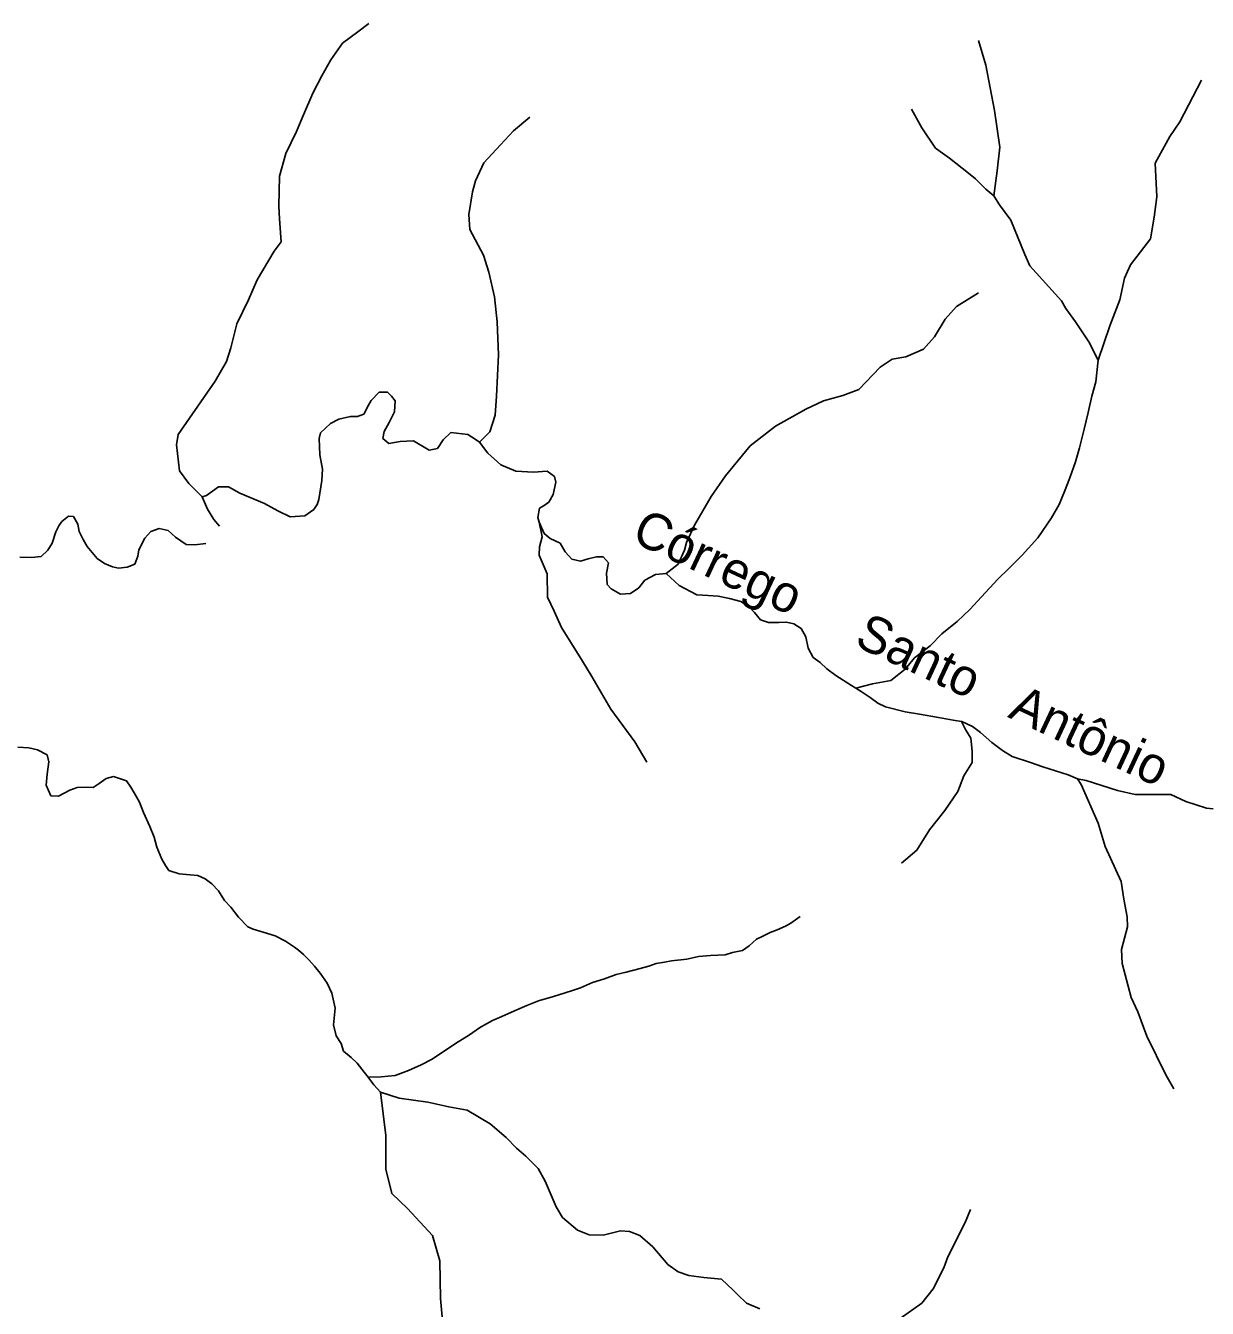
# Model space of a CAD drawing. Extents: x 717.8 to 772.7, y 8672.2 to 8728.
# Drawn here: x 755.19 to 761.61, y 8693.87 to 8700.84 of the extents above; entities that cross this region are included whole.
import ezdxf
from ezdxf.enums import TextEntityAlignment as Align

# ---------------------------------------------------------------- set-up
doc = ezdxf.new("R2010")
doc.units = 0
doc.header["$LTSCALE"] = 0.08
doc.linetypes.add('LONG_DASHED', pattern=[7.5, 6, -1.5])
doc.layers.add('61', color=7, linetype='Continuous')
doc.layers.add('9', color=7, linetype='LONG_DASHED', lineweight=25)

msp = doc.modelspace()

# ---------------------------------------------------------------- linework, layer by layer
at = {"layer": '9'}
for points in [[(757.05, 8700.8522), (756.9906, 8700.8076), (756.9081, 8700.7469), (756.8446, 8700.6562), (756.7959, 8700.5686), (756.7458, 8700.4736), (756.6961, 8700.3565), (756.6567, 8700.2658), (756.5987, 8700.1461), (756.5654, 8700.0229), (756.5623, 8699.86), (756.566, 8699.7909), (756.5738, 8699.6668), (756.5367, 8699.6149), (756.4442, 8699.4594), (756.3961, 8699.3508), (756.3332, 8699.2212), (756.2999, 8699.0904), (756.2778, 8699.0164), (756.2161, 8698.909), (756.0755, 8698.7078), (756.015, 8698.619), (756.0052, 8698.5635), (756.0226, 8698.4224), (756.0718, 8698.352), (756.1444, 8698.2809)], [(760.3633, 8700.7609), (760.4041, 8700.6264), (760.4504, 8700.3804), (760.4801, 8700.1802), (760.4658, 8700.053), (760.447, 8699.9155)], [(761.576, 8700.5442), (761.4576, 8700.3183), (761.4027, 8700.2393), (761.3237, 8700.0933), (761.333, 8699.9108), (761.3182, 8699.7995), (761.2987, 8699.6834), (761.1902, 8699.5413), (761.1567, 8699.4685), (761.1313, 8699.3518), (761.0781, 8699.2106), (761.0145, 8699.0224)], [(759.9994, 8700.3873), (760.0551, 8700.2855), (760.1298, 8700.1754), (760.2057, 8700.1212), (760.3095, 8700.0395), (760.3477, 8700.009), (760.403, 8699.9532), (760.447, 8699.9155)], [(757.9263, 8700.3432), (757.8373, 8700.269), (757.7667, 8700.1937), (757.6757, 8700.0949), (757.6302, 8699.9979), (757.614, 8699.9378), (757.5942, 8699.8141), (757.5994, 8699.7342), (757.6736, 8699.5941), (757.7032, 8699.5015), (757.7332, 8699.3667), (757.7487, 8699.231), (757.7547, 8699.0529), (757.7436, 8698.8266), (757.7367, 8698.7244), (757.7079, 8698.6338), (757.6519, 8698.5771)], [(760.447, 8699.9155), (760.4778, 8699.8677), (760.5395, 8699.784), (760.6156, 8699.598), (760.6418, 8699.5351), (760.8152, 8699.3451), (760.8389, 8699.304), (760.8904, 8699.2309), (760.9639, 8699.1226), (761.0145, 8699.0224)], [(760.363, 8699.3883), (760.2438, 8699.3147), (760.1831, 8699.2464), (760.1237, 8699.1501), (760.0643, 8699.0833), (759.9681, 8699.0408), (759.8937, 8699.0281), (759.8294, 8698.985), (759.7128, 8698.8632), (759.6265, 8698.8316), (759.5217, 8698.8015), (759.4261, 8698.7576), (759.261, 8698.6642), (759.1233, 8698.5578), (758.9882, 8698.3948), (758.9104, 8698.2823), (758.8207, 8698.1269), (758.7776, 8698.0328), (758.7657, 8697.9897), (758.7312, 8697.9144), (758.667, 8697.864), (758.6668, 8697.8639)], [(761.0145, 8699.0224), (761.0008, 8698.9053), (760.9798, 8698.8281), (760.9588, 8698.7392), (760.9378, 8698.6479), (760.9126, 8698.5459), (760.8911, 8698.4701), (760.8598, 8698.3829), (760.8304, 8698.3088), (760.8017, 8698.2395), (760.7595, 8698.1664), (760.6864, 8698.0577), (760.6011, 8697.963), (760.5293, 8697.8902), (760.4686, 8697.8319), (760.3795, 8697.7367), (760.3169, 8697.6683), (760.2479, 8697.6033), (760.1636, 8697.5349), (760.1008, 8697.471), (760.0156, 8697.4054), (759.965, 8697.3435), (759.8863, 8697.2817), (759.7872, 8697.2642), (759.6971, 8697.2409)], [(757.6519, 8698.5771), (757.6277, 8698.593), (757.5882, 8698.6196), (757.4954, 8698.6302), (757.4552, 8698.5904), (757.4234, 8698.5423), (757.3784, 8698.5338), (757.2931, 8698.5846), (757.221, 8698.5803), (757.1586, 8698.571), (757.1271, 8698.5982), (757.1341, 8698.6362), (757.1613, 8698.6835), (757.19, 8698.7417), (757.1931, 8698.8022), (757.1743, 8698.828), (757.1512, 8698.8495), (757.1068, 8698.8499), (757.0635, 8698.8037), (757.0488, 8698.7781), (757.0232, 8698.73), (756.9888, 8698.7167), (756.9517, 8698.7166), (756.8882, 8698.703), (756.8424, 8698.6789), (756.7885, 8698.6275), (756.7812, 8698.5975), (756.7819, 8698.554), (756.7835, 8698.5083), (756.7982, 8698.4314), (756.7951, 8698.3694), (756.7796, 8698.2651), (756.7705, 8698.2383), (756.7517, 8698.212), (756.7021, 8698.1771), (756.6226, 8698.1721), (756.5563, 8698.2034), (756.4841, 8698.2438), (756.3492, 8698.2996), (756.2874, 8698.3341), (756.2329, 8698.3345), (756.1685, 8698.288), (756.1444, 8698.2809)], [(757.9761, 8698.1433), (757.9696, 8698.1671), (757.9786, 8698.2191), (758.0035, 8698.2332), (758.0286, 8698.2522), (758.0514, 8698.2931), (758.0663, 8698.3598), (758.0595, 8698.3903), (758.02, 8698.4195), (757.9445, 8698.4143), (757.8491, 8698.4189), (757.7676, 8698.4547), (757.6972, 8698.5174), (757.6519, 8698.5771)], [(756.1444, 8698.2809), (756.1732, 8698.2139), (756.2087, 8698.1567), (756.2391, 8698.1204)], [(755.1532, 8697.952), (755.2176, 8697.9505), (755.2703, 8697.9551), (755.3061, 8697.99), (755.3302, 8698.028), (755.3488, 8698.0893), (755.3658, 8698.1219), (755.3821, 8698.1467), (755.4178, 8698.1754), (755.4458, 8698.1727), (755.4696, 8698.1322), (755.4768, 8698.0916), (755.4984, 8698.049), (755.5198, 8698.0109), (755.5745, 8697.9458), (755.6133, 8697.9179), (755.6582, 8697.8992), (755.6908, 8697.893), (755.7373, 8697.8977), (755.7792, 8697.914), (755.7954, 8697.9585), (755.8002, 8697.9923), (755.8335, 8698.0552), (755.8661, 8698.0917), (755.9103, 8698.1088), (755.9597, 8698.0971), (756.0002, 8698.0613), (756.0576, 8698.0219), (756.1057, 8698.0203), (756.1654, 8698.0265)], [(758.562, 8696.8379), (758.4969, 8696.9486), (758.365, 8697.127), (758.3145, 8697.213), (758.2627, 8697.3046), (758.212, 8697.3867), (758.0979, 8697.5694), (758.0582, 8697.659), (758.021, 8697.7351), (758.0204, 8697.8618), (757.9762, 8697.9637), (757.9788, 8698.0092), (757.9916, 8698.0623), (757.9761, 8698.1433)], [(758.6668, 8697.8639), (758.608, 8697.8588), (758.5505, 8697.827), (758.5173, 8697.7859), (758.4733, 8697.754), (758.4183, 8697.7512), (758.3667, 8697.78), (758.3464, 8697.8036), (758.3412, 8697.8656), (758.3524, 8697.9218), (758.3238, 8697.9533), (758.2876, 8697.955), (758.2416, 8697.944), (758.2002, 8697.9313), (758.1536, 8697.941), (758.1179, 8697.9819), (758.0895, 8698.0289), (758.0363, 8698.053), (758.0035, 8698.0811), (757.9761, 8698.1433)], [(758.6668, 8697.8639), (758.7378, 8697.7977), (758.8325, 8697.7478), (758.8943, 8697.7449), (758.948, 8697.7402), (759.0109, 8697.7285), (759.0715, 8697.7121), (759.1158, 8697.684), (759.146, 8697.6512), (759.1787, 8697.6114), (759.223, 8697.5974), (759.279, 8697.5974), (759.321, 8697.5997), (759.3606, 8697.5903), (759.4002, 8697.5646), (759.4258, 8697.5201), (759.4384, 8697.4569), (759.4646, 8697.4063), (759.5027, 8697.3798), (759.5395, 8697.3461), (759.589, 8697.3095), (759.6729, 8697.2557), (759.6971, 8697.2409)], [(759.6971, 8697.2409), (759.7266, 8697.2229), (759.7755, 8697.1901), (759.8167, 8697.1582), (759.859, 8697.1388), (759.9655, 8697.1109), (760.043, 8697.0996), (760.1457, 8697.0808), (760.2268, 8697.0657), (760.2721, 8697.0588)], [(759.9454, 8696.289), (760.0288, 8696.3599), (760.0981, 8696.4699), (760.1801, 8696.5756), (760.252, 8696.6787), (760.2841, 8696.7642), (760.329, 8696.8369), (760.3284, 8696.8988), (760.3226, 8696.9689), (760.2923, 8697.0157), (760.2721, 8697.0588)], [(760.2721, 8697.0588), (760.2735, 8697.0586), (760.3318, 8697.0328), (760.3738, 8696.9999), (760.4355, 8696.9443), (760.4939, 8696.902), (760.5471, 8696.869), (760.6466, 8696.8359), (760.7132, 8696.8125), (760.8505, 8696.7692), (760.9022, 8696.7484)], [(755.1424, 8696.9194), (755.2021, 8696.9163), (755.2504, 8696.9047), (755.3026, 8696.8786), (755.3123, 8696.8395), (755.3026, 8696.7737), (755.2967, 8696.7123), (755.3216, 8696.6549), (755.365, 8696.6541), (755.4263, 8696.6867), (755.4662, 8696.7011), (755.5139, 8696.7014), (755.5518, 8696.7012), (755.5851, 8696.7227), (755.6232, 8696.749), (755.6628, 8696.7611), (755.7334, 8696.7371), (755.7564, 8696.7014), (755.7873, 8696.649), (755.8039, 8696.6215), (755.8264, 8696.5641), (755.8613, 8696.4889), (755.8838, 8696.4299), (755.8978, 8696.3756), (755.9257, 8696.3104), (755.9465, 8696.2773), (755.9637, 8696.2491), (756.0192, 8696.2304), (756.0801, 8696.2259), (756.1212, 8696.2227), (756.1607, 8696.2049), (756.1972, 8696.1762), (756.2344, 8696.1382), (756.267, 8696.0854), (756.3, 8696.0496), (756.3428, 8695.9949), (756.3926, 8695.9435), (756.4221, 8695.9303), (756.4756, 8695.914), (756.5423, 8695.8938), (756.5974, 8695.8659), (756.647, 8695.8333), (756.6687, 8695.817), (756.6952, 8695.7928), (756.7237, 8695.7642), (756.7547, 8695.7285), (756.7857, 8695.6905), (756.8236, 8695.6376), (756.8504, 8695.5829), (756.8677, 8695.5014), (756.8593, 8695.4108), (756.8727, 8695.3515), (756.901, 8695.3086), (756.913, 8695.2677), (756.9554, 8695.2331), (756.9868, 8695.2014), (757.0249, 8695.1539), (757.0466, 8695.1264)], [(761.6383, 8696.5849), (761.6018, 8696.5876), (761.4904, 8696.6249), (761.4087, 8696.6621), (761.2158, 8696.6625), (761.1192, 8696.6849), (760.9494, 8696.7388), (760.9022, 8696.7484)], [(761.4253, 8695.0627), (761.382, 8695.1387), (761.2781, 8695.3495), (761.2299, 8695.4804), (761.1925, 8695.5583), (761.1444, 8695.7431), (761.1415, 8695.8201), (761.1741, 8695.9433), (761.1721, 8695.9981), (761.153, 8696.0944), (761.1395, 8696.1887), (761.0528, 8696.3802), (761.0135, 8696.5074), (760.9215, 8696.716), (760.9022, 8696.7484)], [(757.0466, 8695.1264), (757.1177, 8695.1277), (757.1939, 8695.135), (757.2654, 8695.1614), (757.3344, 8695.1924), (757.3939, 8695.2235), (757.468, 8695.2733), (757.5354, 8695.3173), (757.5916, 8695.3524), (757.6582, 8695.3973), (757.7221, 8695.4338), (757.7726, 8695.455), (757.8417, 8695.486), (757.9095, 8695.5161), (757.973, 8695.5407), (758.054, 8695.5645), (758.1511, 8695.5955), (758.2017, 8695.6123), (758.266, 8695.641), (758.3315, 8695.6607), (758.3947, 8695.6839), (758.4497, 8695.6967), (758.5256, 8695.7173), (758.573, 8695.7298), (758.6116, 8695.7436), (758.6569, 8695.7507), (758.6958, 8695.7584), (758.778, 8695.767), (758.8428, 8695.7817), (758.9071, 8695.7865), (758.9864, 8695.7915), (759.0263, 8695.8032), (759.081, 8695.8151), (759.1172, 8695.84), (759.1566, 8695.8766), (759.1836, 8695.8889), (759.2313, 8695.9128), (759.2694, 8695.9271), (759.3147, 8695.9461), (759.3433, 8695.9628), (759.3937, 8695.9995)], [(757.0466, 8695.1264), (757.0512, 8695.1205), (757.0773, 8695.0848), (757.1142, 8695.0451)], [(757.4485, 8693.8234), (757.44, 8693.9226), (757.4369, 8694.1274), (757.3957, 8694.2648), (757.2608, 8694.4129), (757.1762, 8694.4936), (757.1422, 8694.6255), (757.1422, 8694.8094), (757.1142, 8695.0451)], [(759.1758, 8693.8676), (759.103, 8693.8979), (759.0545, 8693.9442), (759.0296, 8693.9689), (758.9663, 8694.0273), (758.8715, 8694.0364), (758.7898, 8694.0487), (758.731, 8694.0684), (758.6756, 8694.1072), (758.5934, 8694.2044), (758.5232, 8694.2651), (758.4677, 8694.2873), (758.4186, 8694.2902), (758.3238, 8694.2679), (758.2472, 8694.2685), (758.1839, 8694.2948), (758.1038, 8694.3633), (758.0681, 8694.4207), (758.0087, 8694.5615), (757.9715, 8694.6295), (757.9033, 8694.6975), (757.8537, 8694.7407), (757.796, 8694.7975), (757.7092, 8694.8727), (757.5852, 8694.9467), (757.486, 8694.9652), (757.371, 8694.9906), (757.2156, 8695.0123), (757.1142, 8695.0451)], [(760.3198, 8694.4064), (760.2919, 8694.3353), (760.1975, 8694.1504), (760.1749, 8694.0897), (760.1174, 8693.9761), (760.0561, 8693.8986), (759.9372, 8693.8135), (759.8242, 8693.7799)]]:
    msp.add_lwpolyline(points, dxfattribs=at)

# ---------------------------------------------------------------- texts
at = {"layer": '61'}
msp.add_text('Córrego     Santo   Antônio', height=0.2, rotation=334.96, dxfattribs=at).set_placement((759.9046, 8697.3709), align=Align.CENTER)

doc.saveas('drawing.dxf')
